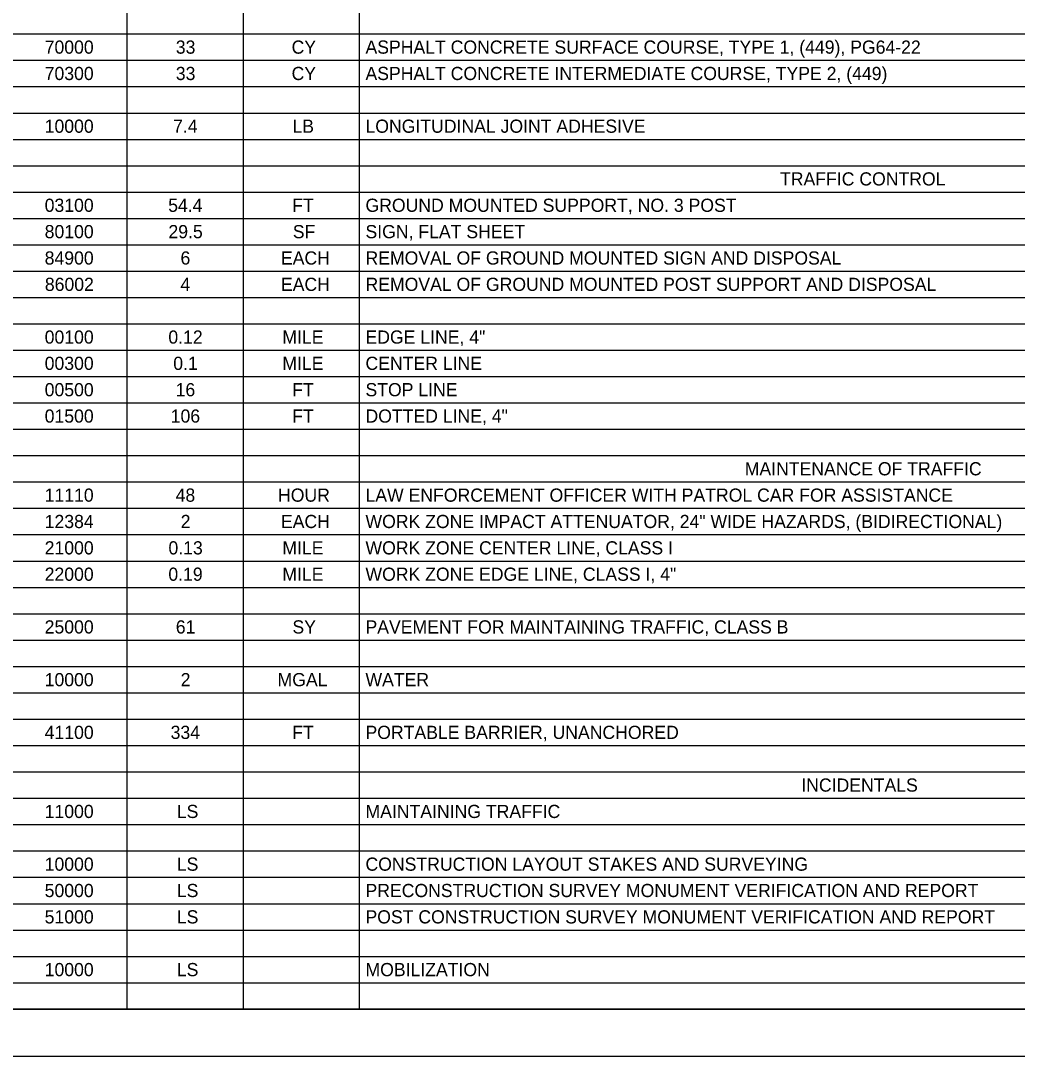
# Model space of a CAD drawing. Extents: x 0 to 34, y 0 to 22.
# Drawn here: x 16.91 to 27.5, y 0 to 11 of the extents above; entities that cross this region are included whole.
import ezdxf

# ---------------------------------------------------------------- set-up
doc = ezdxf.new("R2010")
doc.units = 0
for name, color, linetype in [('Default', 7, 'Continuous'), ('SH_Border', 7, 'Continuous'), ('SH_Cut_Line', 7, 'Continuous')]:
    doc.layers.add(name, color=color, linetype=linetype)

msp = doc.modelspace()

# ---------------------------------------------------------------- linework, layer by layer
at = {"layer": 'Default'}
for p, q in [((18.036, 21.5), (18.036, 0.501)), ((19.271, 21.5), (19.271, 0.501)), ((20.506, 21.5), (20.506, 0.501)), ((1.5, 10.86), (32.002, 10.86)), ((1.5, 10.58), (32.002, 10.58)), ((1.5, 10.3), (32.002, 10.3)), ((1.5, 10.02), (32.002, 10.02)), ((1.5, 9.74), (32.002, 9.74)), ((1.5, 9.46), (32.002, 9.46)), ((1.5, 9.18), (32.002, 9.18)), ((1.5, 8.9), (32.002, 8.9)), ((1.5, 8.62), (32.002, 8.62)), ((1.5, 8.34), (32.002, 8.34)), ((1.5, 8.06), (32.002, 8.06)), ((1.5, 7.78), (32.002, 7.78)), ((1.5, 7.5), (32.002, 7.5)), ((1.5, 7.221), (32.002, 7.221)), ((1.5, 6.941), (32.002, 6.941)), ((1.5, 6.661), (32.002, 6.661)), ((1.5, 6.381), (32.002, 6.381)), ((1.5, 6.101), (32.002, 6.101)), ((1.5, 5.821), (32.002, 5.821)), ((1.5, 5.541), (32.002, 5.541)), ((1.5, 5.261), (32.002, 5.261)), ((1.5, 4.981), (32.002, 4.981)), ((1.5, 4.701), (32.002, 4.701)), ((1.5, 4.421), (32.002, 4.421)), ((1.5, 4.141), (32.002, 4.141)), ((1.5, 3.861), (32.002, 3.861)), ((1.5, 3.581), (32.002, 3.581)), ((1.5, 3.301), (32.002, 3.301)), ((1.5, 3.021), (32.002, 3.021)), ((1.5, 2.741), (32.002, 2.741)), ((1.5, 2.461), (32.002, 2.461)), ((1.5, 2.181), (32.002, 2.181)), ((1.5, 1.901), (32.002, 1.901)), ((1.5, 1.621), (32.002, 1.621)), ((1.5, 1.341), (32.002, 1.341)), ((1.5, 1.061), (32.002, 1.061)), ((1.5, 0.781), (32.002, 0.781)), ((1.5, 0.501), (32.002, 0.501))]:
    msp.add_line(p, q, dxfattribs=at)
at = {"layer": 'SH_Border'}
msp.add_lwpolyline([(1.5, 21.5), (33.5, 21.5), (33.5, 0.5), (1.5, 0.5)], close=True, dxfattribs=at)
at = {"layer": 'SH_Cut_Line'}
msp.add_lwpolyline([(0, 0), (34, 0), (34, 22), (0, 22)], close=True, dxfattribs=at)

# ---------------------------------------------------------------- texts
at = {"layer": 'Default'}
for s, p in [('70000', (17.164, 10.65)), ('33', (18.557, 10.65)), ('CY', (19.787, 10.65)), ('ASPHALT CONCRETE SURFACE COURSE, TYPE 1, (449), PG64-22', (20.572, 10.65)), ('70300', (17.164, 10.37)), ('33', (18.557, 10.37)), ('CY', (19.787, 10.37)), ('ASPHALT CONCRETE INTERMEDIATE COURSE, TYPE 2, (449)', (20.572, 10.37)), ('10000', (17.164, 9.81)), ('7.4', (18.528, 9.81)), ('LB', (19.796, 9.81)), ('LONGITUDINAL JOINT ADHESIVE', (20.572, 9.81)), ('TRAFFIC CONTROL', (24.976, 9.25)), ('03100', (17.164, 8.97)), ('54.4', (18.476, 8.97)), ('FT', (19.794, 8.97)), ('GROUND MOUNTED SUPPORT, NO. 3 POST', (20.572, 8.97)), ('80100', (17.164, 8.69)), ('29.5', (18.479, 8.69)), ('SF', (19.8, 8.69)), ('SIGN, FLAT SHEET', (20.572, 8.69)), ('84900', (17.164, 8.41)), ('6', (18.607, 8.41)), ('EACH', (19.674, 8.41)), ('REMOVAL OF GROUND MOUNTED SIGN AND DISPOSAL', (20.572, 8.41)), ('86002', (17.166, 8.13)), ('4', (18.606, 8.13)), ('EACH', (19.674, 8.13)), ('REMOVAL OF GROUND MOUNTED POST SUPPORT AND DISPOSAL', (20.572, 8.13)), ('00100', (17.164, 7.57)), ('0.12', (18.478, 7.57)), ('MILE', (19.689, 7.57)), ('EDGE LINE, 4"', (20.572, 7.57)), ('00300', (17.164, 7.291)), ('0.1', (18.53, 7.291)), ('MILE', (19.689, 7.291)), ('CENTER LINE', (20.572, 7.291)), ('00500', (17.164, 7.011)), ('16', (18.555, 7.011)), ('FT', (19.794, 7.011)), ('STOP LINE', (20.572, 7.011)), ('01500', (17.164, 6.731)), ('106', (18.503, 6.731)), ('FT', (19.794, 6.731)), ('DOTTED LINE, 4"', (20.572, 6.731)), ('MAINTENANCE OF TRAFFIC', (24.601, 6.171)), ('11110', (17.164, 5.891)), ('48', (18.555, 5.891)), ('HOUR', (19.643, 5.891)), ('LAW ENFORCEMENT OFFICER WITH PATROL CAR FOR ASSISTANCE', (20.572, 5.891)), ('12384', (17.164, 5.611)), ('2', (18.609, 5.611)), ('EACH', (19.674, 5.611)), ('WORK ZONE IMPACT ATTENUATOR, 24" WIDE HAZARDS, (BIDIRECTIONAL)', (20.572, 5.611)), ('21000', (17.164, 5.331)), ('0.13', (18.479, 5.331)), ('MILE', (19.689, 5.331)), ('WORK ZONE CENTER LINE, CLASS I', (20.572, 5.331)), ('22000', (17.164, 5.051)), ('0.19', (18.478, 5.051)), ('MILE', (19.689, 5.051)), ('WORK ZONE EDGE LINE, CLASS I, 4"', (20.572, 5.051)), ('25000', (17.164, 4.491)), ('61', (18.557, 4.491)), ('SY', (19.796, 4.491)), ('PAVEMENT FOR MAINTAINING TRAFFIC, CLASS B', (20.572, 4.491)), ('10000', (17.164, 3.931)), ('2', (18.609, 3.931)), ('MGAL', (19.638, 3.931)), ('WATER', (20.572, 3.931)), ('41100', (17.164, 3.371)), ('334', (18.502, 3.371)), ('FT', (19.794, 3.371)), ('PORTABLE BARRIER, UNANCHORED', (20.572, 3.371)), ('INCIDENTALS', (25.202, 2.811)), ('11000', (17.164, 2.531)), ('LS', (18.568, 2.531)), ('MAINTAINING TRAFFIC', (20.572, 2.531)), ('10000', (17.164, 1.971)), ('LS', (18.568, 1.971)), ('CONSTRUCTION LAYOUT STAKES AND SURVEYING', (20.572, 1.971)), ('50000', (17.164, 1.691)), ('LS', (18.568, 1.691)), ('PRECONSTRUCTION SURVEY MONUMENT VERIFICATION AND REPORT', (20.572, 1.691)), ('51000', (17.164, 1.411)), ('LS', (18.568, 1.411)), ('POST CONSTRUCTION SURVEY MONUMENT VERIFICATION AND REPORT', (20.572, 1.411)), ('10000', (17.164, 0.851)), ('LS', (18.568, 0.851)), ('MOBILIZATION', (20.572, 0.851))]:
    msp.add_text(s, height=0.14, dxfattribs=at).set_placement(p)

doc.saveas('drawing.dxf')
